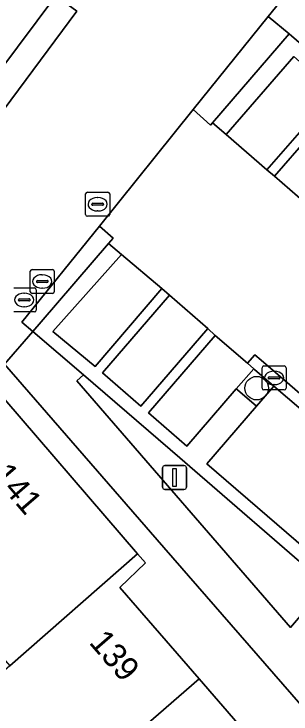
# Model space of a CAD drawing. Extents: x 161881 to 162523, y 381678 to 382381.
# Drawn here: x 161990.42 to 162001.95, y 382171.7 to 382200.83 of the extents above; entities that cross this region are included whole.
import ezdxf

# ---------------------------------------------------------------- set-up
doc = ezdxf.new("R2010")
doc.units = 0
for name, color, linetype in [('IMGEO_Boom', 7, 'Continuous'), ('IMGEO_Erf', 7, 'Continuous'), ('IMGEO_Groenvoorziening', 7, 'Continuous'), ('IMGEO_Kolk', 7, 'Continuous'), ('IMGEO_Lichtmast', 7, 'Continuous'), ('IMGEO_Pand', 7, 'Continuous'), ('IMGEO_Pand_nummerreeks', 7, 'Continuous'), ('IMGEO_Parkeervlak_open', 7, 'Continuous'), ('IMGEO_Rijbaan_lokaal_open', 7, 'Continuous'), ('IMGEO_Rioolput', 7, 'Continuous'), ('IMGEO_Voetpad_open', 7, 'Continuous')]:
    doc.layers.add(name, color=color, linetype=linetype)

msp = doc.modelspace()

# ---------------------------------------------------------------- linework, layer by layer
at = {"layer": 'IMGEO_Boom'}
msp.add_circle((162000.518, 382185.259), 0.489, dxfattribs=at)
at = {"layer": 'IMGEO_Erf'}
for points in [[(162030.201, 382140.112), (161996.66, 382178.627), (161990.016, 382186.254), (161988.587, 382187.894), (161980.177, 382180.625), (161980.188, 382180.574), (161984.998, 382159.715), (161990.302, 382150.73)], [(161989.336, 382185.574), (161995.56, 382178.365), (161995.886, 382177.987), (161994.815, 382176.958), (161998.118, 382173.163), (162001.169, 382169.656), (162004.5, 382165.829), (162007.819, 382162.014), (162011.263, 382158.057), (162014.672, 382154.139), (162018.08, 382150.222)]]:
    msp.add_lwpolyline(points, dxfattribs=at)
at = {"layer": 'IMGEO_Groenvoorziening'}
for points in [[(162001.236, 382185.346), (162000.428, 382186.035), (162000.395, 382186.065), (161999.669, 382185.228), (161999.714, 382185.19), (162000.513, 382184.511)], [(161997.32, 382182.356), (161993.312, 382185.812), (161993.031, 382185.565), (162001.926, 382175.294), (162003.438, 382177.057)]]:
    msp.add_lwpolyline(points, close=True, dxfattribs=at)
at = {"layer": 'IMGEO_Kolk'}
for p, q in [((162000.742, 382185.26), (162000.742, 382186.112)), ((162000.817, 382186.186), (162001.669, 382186.186)), ((162001.743, 382186.112), (162001.743, 382185.26)), ((162001.044, 382185.729), (162001.442, 382185.729)), ((162001.23, 382185.966), (162001.255, 382185.966)), ((162001.001, 382185.68), (162001.001, 382185.692)), ((162001.439, 382185.643), (162001.041, 382185.643)), ((162001.485, 382185.692), (162001.485, 382185.68)), ((162001.669, 382185.186), (162000.817, 382185.186)), ((162001.253, 382185.406), (162001.228, 382185.406))]:
    msp.add_line(p, q, dxfattribs=at)
for points in [[(162000.742, 382185.26), (162000.742, 382186.112)], [(162000.817, 382186.186), (162001.669, 382186.186)], [(162001.743, 382186.112), (162001.743, 382185.26)], [(162001.669, 382185.186), (162000.817, 382185.186)]]:
    msp.add_lwpolyline(points, dxfattribs=at)
for centre, radius, start, end in [((162000.819, 382186.11), 0.0765, 91.552, 178.448), ((162000.819, 382186.11), 0.0765, 91.552, 178.448), ((162001.667, 382186.11), 0.0765, 1.552, 88.448), ((162001.667, 382186.11), 0.0765, 1.552, 88.448), ((162001.041, 382185.689), 0.0403, 85.8775, 175.7526), ((162001.446, 382185.691), 0.0386, 1.7309, 96.639), ((162001.038, 382185.679), 0.0366, 178.938, 274.7102), ((162001.442, 382185.686), 0.043, 264.8664, 352.4533), ((162000.819, 382185.262), 0.0765, 181.552, 268.448), ((162000.819, 382185.262), 0.0765, 181.552, 268.448), ((162001.667, 382185.262), 0.0765, 271.552, 358.448), ((162001.667, 382185.262), 0.0765, 271.552, 358.448)]:
    msp.add_arc(centre, radius, start, end, dxfattribs=at)
for centre, major_axis, ratio, start_param, end_param in [((162001.229, 382185.686), (-0.387, 0.002), 0.722429, 4.712389, 7.853982), ((162001.254, 382185.686), (-0.39, 0.002), 0.717154, 1.570796, 4.712389)]:
    msp.add_ellipse(centre, major_axis=major_axis, ratio=ratio, start_param=start_param, end_param=end_param, dxfattribs=at)
at = {"layer": 'IMGEO_Lichtmast'}
for p, q in [((161996.602, 382181.142), (161996.602, 382181.942)), ((161996.602, 382181.942), (161996.602, 382181.142)), ((161996.702, 382182.042), (161997.492, 382182.042)), ((161997.492, 382182.042), (161996.702, 382182.042)), ((161997.592, 382181.942), (161997.592, 382181.142)), ((161997.592, 382181.142), (161997.592, 382181.942)), ((161997.492, 382181.042), (161996.702, 382181.042)), ((161996.702, 382181.042), (161997.492, 382181.042))]:
    msp.add_line(p, q, dxfattribs=at)
msp.add_lwpolyline([(161997.022, 382181.917), (161997.172, 382181.917), (161997.172, 382181.167), (161997.022, 382181.167), (161997.022, 382181.917)], dxfattribs=at)
for centre, start, end in [((161996.702, 382181.942), 90, 180), ((161996.702, 382181.942), 90, 180), ((161997.492, 382181.942), 0, 90), ((161997.492, 382181.942), 360, 90), ((161996.702, 382181.142), 180, 270), ((161996.702, 382181.142), 180, 270), ((161997.492, 382181.142), 270, 0), ((161997.492, 382181.142), 270, 0)]:
    msp.add_arc(centre, 0.1, start, end, dxfattribs=at)
at = {"layer": 'IMGEO_Pand'}
for points in [[(161989.336, 382185.574), (161988.906, 382185.2), (161984.553, 382181.411), (161983.97, 382180.903), (161984.547, 382180.24), (161984.955, 382179.772), (161990.236, 382173.705), (161995.56, 382178.365)], [(161998.118, 382173.163), (161994.815, 382176.958), (161995.886, 382177.987), (161995.56, 382178.365), (161990.236, 382173.705), (161987.617, 382171.413), (161985.858, 382169.874), (161985.395, 382169.468), (161986.163, 382168.584), (161988.921, 382165.41), (161989.039, 382165.274), (161989.985, 382166.096)], [(162001.169, 382169.656), (161998.118, 382173.163), (161989.985, 382166.096), (161993.025, 382162.6)]]:
    msp.add_lwpolyline(points, close=True, dxfattribs=at)
at = {"layer": 'IMGEO_Parkeervlak_open'}
for points in [[(162002.065, 382199.055), (161999.247, 382195.812), (162000.943, 382194.34), (162003.754, 382197.564)], [(162004.069, 382197.299), (162001.266, 382194.083), (162002.861, 382192.693), (162005.666, 382195.91)], [(161996.568, 382189.407), (161994.894, 382190.821), (161992.035, 382187.621), (161993.792, 382186.162)], [(161998.481, 382187.74), (161996.883, 382189.128), (161994.099, 382185.902), (161995.691, 382184.507)], [(161999.669, 382185.228), (162000.395, 382186.065), (162000.135, 382186.301), (161998.787, 382187.457), (161996.013, 382184.238), (161997.609, 382182.85)], [(162001.236, 382185.346), (162000.513, 382184.511), (161998.439, 382182.114), (162003.868, 382177.436), (162006.67, 382180.667), (162005.021, 382182.115)]]:
    msp.add_lwpolyline(points, close=True, dxfattribs=at)
at = {"layer": 'IMGEO_Rijbaan_lokaal_open'}
for points in [[(161981.166, 382186.879), (161987.249, 382195.014), (161987.268, 382195.039), (161988.169, 382196.277), (161992.153, 382201.593), (161995.048, 382205.452), (161995.464, 382205.989), (162010.665, 382226.206), (162014.591, 382231.432), (162019.647, 382238.162), (162020.575, 382239.149), (162021.178, 382239.811)], [(162002.861, 382192.693), (162001.266, 382194.083), (162000.943, 382194.34), (161999.247, 382195.812), (161998.681, 382196.303), (161998.597, 382196.205), (161997.877, 382196.852), (161993.971, 382192.007), (161994.548, 382191.496), (161994.357, 382191.275), (161994.894, 382190.821), (161996.568, 382189.407), (161996.883, 382189.128), (161998.481, 382187.74), (161998.787, 382187.457), (162000.135, 382186.301), (162000.438, 382186.65), (162000.705, 382186.422), (162001.899, 382185.403), (162036.967, 382155.028)]]:
    msp.add_lwpolyline(points, dxfattribs=at)
msp.add_lwpolyline([(162001.899, 382185.403), (162000.705, 382186.422), (162000.438, 382186.65), (162000.135, 382186.301), (162000.395, 382186.065), (162000.428, 382186.035), (162001.236, 382185.346), (162005.021, 382182.115), (162006.67, 382180.667), (162007.638, 382179.817), (162013.107, 382175.099), (162013.934, 382174.385), (162019.379, 382169.666), (162020.364, 382168.811), (162025.835, 382164.089), (162026.682, 382163.354), (162032.109, 382158.646), (162033.054, 382157.803), (162036.646, 382154.691), (162036.967, 382155.028)], close=True, dxfattribs=at)
at = {"layer": 'IMGEO_Rioolput'}
for p, q in [((161993.398, 382192.488), (161993.398, 382193.34)), ((161993.473, 382193.414), (161994.325, 382193.414)), ((161994.399, 382193.34), (161994.399, 382192.488)), ((161993.886, 382193.194), (161993.911, 382193.194)), ((161993.657, 382192.908), (161993.657, 382192.92)), ((161994.095, 382192.871), (161993.697, 382192.871)), ((161993.7, 382192.957), (161994.098, 382192.957)), ((161994.141, 382192.92), (161994.141, 382192.908)), ((161994.325, 382192.414), (161993.473, 382192.414)), ((161993.909, 382192.634), (161993.884, 382192.634)), ((161991.093, 382189.272), (161991.093, 382190.124)), ((161991.168, 382190.198), (161992.02, 382190.198)), ((161992.094, 382190.124), (161992.094, 382189.272)), ((161991.581, 382189.978), (161991.606, 382189.978)), ((161991.352, 382189.692), (161991.352, 382189.704)), ((161991.79, 382189.655), (161991.392, 382189.655)), ((161991.395, 382189.741), (161991.793, 382189.741)), ((161991.836, 382189.704), (161991.836, 382189.692)), ((161990.416, 382189.43), (161991.268, 382189.43)), ((161990.829, 382189.21), (161990.854, 382189.21)), ((161991.342, 382189.356), (161991.342, 382188.504)), ((161991.604, 382189.418), (161991.579, 382189.418)), ((161990.6, 382188.924), (161990.6, 382188.936)), ((161990.643, 382188.973), (161991.041, 382188.973)), ((161991.084, 382188.936), (161991.084, 382188.924)), ((161992.02, 382189.198), (161991.168, 382189.198)), ((161991.038, 382188.887), (161990.64, 382188.887)), ((161990.852, 382188.65), (161990.827, 382188.65)), ((161991.268, 382188.43), (161990.416, 382188.43))]:
    msp.add_line(p, q, dxfattribs=at)
for points in [[(161993.398, 382192.488), (161993.398, 382193.34)], [(161993.473, 382193.414), (161994.325, 382193.414)], [(161994.399, 382193.34), (161994.399, 382192.488)], [(161994.325, 382192.414), (161993.473, 382192.414)], [(161991.093, 382189.272), (161991.093, 382190.124)], [(161991.168, 382190.198), (161992.02, 382190.198)], [(161992.094, 382190.124), (161992.094, 382189.272)], [(161990.416, 382189.43), (161991.268, 382189.43)], [(161991.342, 382189.356), (161991.342, 382188.504)], [(161992.02, 382189.198), (161991.168, 382189.198)], [(161991.268, 382188.43), (161990.416, 382188.43)]]:
    msp.add_lwpolyline(points, dxfattribs=at)
for centre, radius, start, end in [((161993.475, 382193.338), 0.0765, 91.552, 178.448), ((161993.475, 382193.338), 0.0765, 91.552, 178.448), ((161994.323, 382193.338), 0.0765, 1.552, 88.448), ((161994.323, 382193.338), 0.0765, 1.552, 88.448), ((161993.697, 382192.917), 0.0403, 85.8775, 175.7526), ((161993.694, 382192.907), 0.0366, 178.938, 274.7102), ((161994.098, 382192.914), 0.043, 264.8664, 352.4533), ((161994.102, 382192.919), 0.0386, 1.7309, 96.639), ((161993.475, 382192.49), 0.0765, 181.552, 268.448), ((161993.475, 382192.49), 0.0765, 181.552, 268.448), ((161994.323, 382192.49), 0.0765, 271.552, 358.448), ((161994.323, 382192.49), 0.0765, 271.552, 358.448), ((161991.17, 382190.122), 0.0765, 91.552, 178.448), ((161991.17, 382190.122), 0.0765, 91.552, 178.448), ((161992.018, 382190.122), 0.0765, 1.552, 88.448), ((161992.018, 382190.122), 0.0765, 1.552, 88.448), ((161991.392, 382189.701), 0.0403, 85.8775, 175.7526), ((161991.389, 382189.691), 0.0366, 178.938, 274.7102), ((161991.793, 382189.698), 0.043, 264.8664, 352.4533), ((161991.797, 382189.703), 0.0386, 1.7309, 96.639), ((161991.17, 382189.274), 0.0765, 181.552, 268.448), ((161991.17, 382189.274), 0.0765, 181.552, 268.448), ((161991.266, 382189.354), 0.0765, 1.552, 88.448), ((161991.266, 382189.354), 0.0765, 1.552, 88.448), ((161992.018, 382189.274), 0.0765, 271.552, 358.448), ((161992.018, 382189.274), 0.0765, 271.552, 358.448), ((161990.64, 382188.933), 0.0403, 85.8775, 175.7526), ((161990.637, 382188.923), 0.0366, 178.938, 274.7102), ((161991.041, 382188.93), 0.043, 264.8664, 352.4533), ((161991.045, 382188.935), 0.0386, 1.7309, 96.639), ((161991.266, 382188.506), 0.0765, 271.552, 358.448), ((161991.266, 382188.506), 0.0765, 271.552, 358.448)]:
    msp.add_arc(centre, radius, start, end, dxfattribs=at)
for centre, major_axis, ratio, start_param, end_param in [((161993.885, 382192.914), (-0.387, 0.002), 0.722429, 4.712389, 7.853982), ((161993.91, 382192.914), (-0.39, 0.002), 0.717154, 1.570796, 4.712389), ((161991.58, 382189.698), (-0.387, 0.002), 0.722429, 4.712389, 7.853982), ((161991.605, 382189.698), (-0.39, 0.002), 0.717154, 1.570796, 4.712389), ((161990.828, 382188.93), (-0.387, 0.002), 0.722429, 4.712389, 7.853982), ((161990.853, 382188.93), (-0.39, 0.002), 0.717154, 1.570796, 4.712389)]:
    msp.add_ellipse(centre, major_axis=major_axis, ratio=ratio, start_param=start_param, end_param=end_param, dxfattribs=at)
at = {"layer": 'IMGEO_Voetpad_open'}
for points in [[(161995.52, 382206.048), (161995.464, 382205.989), (161995.048, 382205.452), (161992.153, 382201.593), (161993.029, 382200.94), (161989.075, 382195.628), (161990.033, 382194.911), (161988.879, 382193.351), (161987.181, 382194.6), (161987.083, 382194.672)], [(161979.998, 382181.502), (161980.177, 382180.625), (161988.587, 382187.894), (161990.016, 382186.254), (161991.197, 382187.619), (161990.744, 382188.005), (161993.971, 382192.007), (161997.877, 382196.852), (162001.003, 382200.728), (162002.15, 382202.152)], [(162058.69, 382153.142), (162034.901, 382173.742), (162007.715, 382197.353), (162002.15, 382202.152), (162001.003, 382200.728), (162001.87, 382200.001), (162006.547, 382195.968), (162007.937, 382194.769), (162008.089, 382194.637), (162014.192, 382189.336), (162015.213, 382188.449), (162026.877, 382178.317), (162027.903, 382177.426), (162030.56, 382175.118), (162039.593, 382167.298)], [(162006.547, 382195.968), (162001.87, 382200.001), (161998.681, 382196.303), (161999.247, 382195.812), (162002.065, 382199.055)], [(162003.754, 382197.564), (162000.943, 382194.34), (162001.266, 382194.083), (162004.069, 382197.299)], [(162003.868, 382177.436), (161998.439, 382182.114), (162000.513, 382184.511), (161999.714, 382185.19), (161999.669, 382185.228), (161997.609, 382182.85), (161996.013, 382184.238), (161998.787, 382187.457), (161998.481, 382187.74), (161995.691, 382184.507), (161994.099, 382185.902), (161996.883, 382189.128), (161996.568, 382189.407), (161993.792, 382186.162), (161992.035, 382187.621), (161994.894, 382190.821), (161994.357, 382191.275), (161991.548, 382188.025), (161991.197, 382187.619), (161993.312, 382185.812), (161997.32, 382182.356), (162003.438, 382177.057)], [(162025.152, 382148.644), (162029.896, 382154.126), (162029.88, 382154.141), (162028.872, 382155.015), (162028.853, 382155.032), (162024.17, 382149.745), (162014.005, 382161.432), (162017.138, 382165.198), (162016.175, 382166.031), (162016.152, 382166.051), (162013.07, 382162.502), (162002.856, 382174.263), (162004.491, 382176.151), (162004.468, 382176.171), (162003.503, 382177.001), (162003.438, 382177.057), (162001.926, 382175.294), (161993.031, 382185.565), (161993.312, 382185.812), (161991.197, 382187.619), (161990.016, 382186.254), (161996.66, 382178.627), (162030.201, 382140.112)]]:
    msp.add_lwpolyline(points, dxfattribs=at)
for points in [[(161992.153, 382201.593), (161988.169, 382196.277), (161989.075, 382195.628), (161993.029, 382200.94)], [(162001.87, 382200.001), (162001.003, 382200.728), (161997.877, 382196.852), (161998.597, 382196.205), (161998.681, 382196.303)], [(161994.357, 382191.275), (161994.548, 382191.496), (161993.971, 382192.007), (161990.744, 382188.005), (161991.197, 382187.619), (161991.548, 382188.025)]]:
    msp.add_lwpolyline(points, close=True, dxfattribs=at)

# ---------------------------------------------------------------- texts
at = {"layer": 'IMGEO_Pand_nummerreeks'}
for s, rotation, p in [('141', 310.6053, (161989.462, 382181.611)), ('139', 310.8345, (161993.506, 382174.661))]:
    msp.add_text(s, height=1, rotation=rotation, dxfattribs=at).set_placement(p)

doc.saveas('drawing.dxf')
